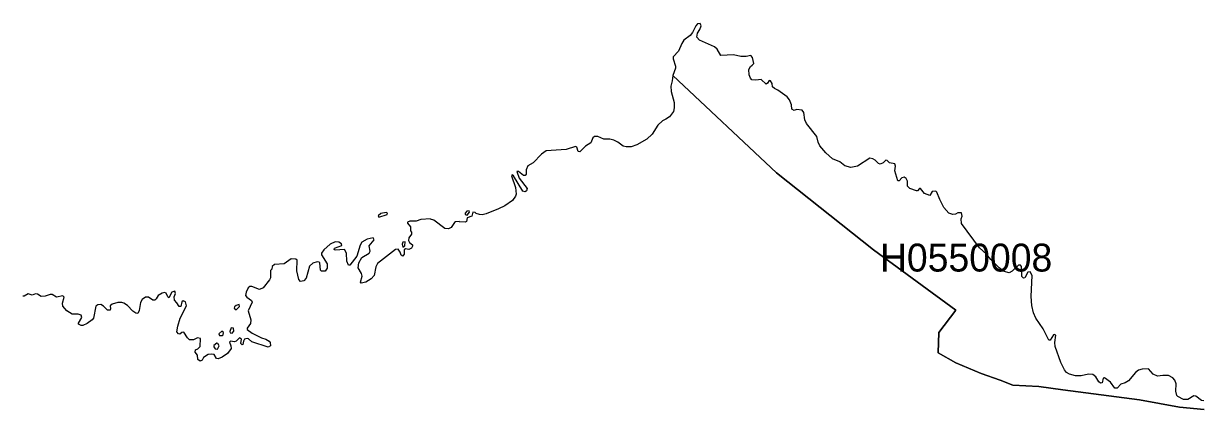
# Model space of a CAD drawing. Extents: x 369010 to 739155, y 6377141 to 6616555.
# Drawn here: x 432217 to 436436, y 6497667 to 6499050 of the extents above; entities that cross this region are included whole.
import ezdxf
from ezdxf.enums import TextEntityAlignment as Align

# ---------------------------------------------------------------- set-up
doc = ezdxf.new("R2010")
doc.units = 0
doc.header["$LTSCALE"] = 40
doc.layers.add('1', color=7, linetype='Continuous', lineweight=13)
doc.layers.add('2', color=7, linetype='Continuous')

msp = doc.modelspace()

# ---------------------------------------------------------------- linework, layer by layer
at = {"layer": '1'}
for points in [[(435305.81, 6498560.18), (435296.05, 6498551.24), (435285.12, 6498546.11), (435278.67, 6498548.27), (435267.08, 6498560.84), (435259.31, 6498565.81), (435248.05, 6498567.96), (435203.86, 6498539), (435180.03, 6498534.2), (435158.84, 6498540.65), (435140.14, 6498554.39), (435114.32, 6498565.15), (435090.16, 6498586.33), (435069.47, 6498612.15), (435063.02, 6498624.4), (435057.89, 6498645.09), (435021.14, 6498692.09), (435015.02, 6498705), (435011.21, 6498730.82), (435006.25, 6498739.42), (434985.06, 6498742.4), (434977.62, 6498739.09), (434968.51, 6498743.39), (434967.69, 6498759.12), (434960.9, 6498776.83), (434951.47, 6498786.92), (434918.37, 6498811.09), (434906.12, 6498816.88), (434900, 6498823.66), (434898.01, 6498834.92), (434892.55, 6498844.85), (434887.09, 6498846.17), (434881.62, 6498836.57), (434877.32, 6498833.26), (434858.95, 6498849.48), (434839.59, 6498847.17), (434825.52, 6498848.82), (434820.06, 6498853.95), (434815.42, 6498866.86), (434814.43, 6498885.23), (434820.22, 6498896.82), (434826.68, 6498900.62), (434832.3, 6498907.41), (434827.67, 6498928.43), (434822.21, 6498936.04), (434804.83, 6498932.23), (434785.47, 6498931.9), (434759.65, 6498938.03), (434714.63, 6498936.04), (434701.06, 6498958.72), (434691.96, 6498966.66), (434638.17, 6498990.99), (434627.91, 6499000.92), (434631.05, 6499016.31), (434639.16, 6499029.22), (434643.63, 6499042.13), (434639.82, 6499050.24), (434631.05, 6499048.92), (434624.6, 6499041.8), (434612.35, 6499018.3), (434604.57, 6499007.7), (434582.39, 6498990.33), (434574.95, 6498978.41), (434563.03, 6498950.94), (434544, 6498930.91), (434543.33, 6498923.63), (434552.44, 6498897.81), (434552.11, 6498890.69), (434542.84, 6498864.38)], [(434542.84, 6498864.38), (434542.67, 6498864.21), (434540.52, 6498844.85), (434534.73, 6498825.48), (434536.88, 6498806.29), (434547.31, 6498767.56), (434547.31, 6498748.19), (434544.66, 6498735.29), (434530.43, 6498716.09), (434517.85, 6498707.15), (434505.1, 6498701.36), (434488.72, 6498686.3), (434468.53, 6498653.69), (434448.83, 6498635.65), (434412.92, 6498615.46), (434393.39, 6498608.18), (434375.68, 6498608.18), (434364.26, 6498610.83), (434345.89, 6498624.89), (434330.66, 6498632.67), (434316.93, 6498635.32), (434295.24, 6498635.98), (434273.73, 6498644.75), (434262.31, 6498645.75), (434256.35, 6498640.29), (434248.24, 6498622.91), (434229.21, 6498610.5), (434209.35, 6498590.3), (434203.89, 6498590.97), (434198.26, 6498606.52), (434193.29, 6498609.5), (434160.69, 6498598.74), (434088.86, 6498593.78), (434071.81, 6498582.03), (434041.69, 6498550.75), (434023.49, 6498539.99), (434016.54, 6498525.26), (434016.87, 6498510.86), (434013.39, 6498504.9), (434007.1, 6498505.9), (433989.56, 6498519.63), (433983.27, 6498519.96), (433991.71, 6498495.8), (434020.84, 6498459.22), (434018.85, 6498450.12), (434013.72, 6498446.48), (434004.78, 6498448.96), (433971.68, 6498504.41), (433966.72, 6498507.55), (433964.57, 6498503.75), (433979.3, 6498462.53), (433981.61, 6498439.03), (433978.97, 6498431.09), (433967.88, 6498415.86), (433940.73, 6498396.83), (433918.23, 6498385.74), (433873.21, 6498367.7), (433859.47, 6498364.23), (433849.71, 6498365.22), (433837.63, 6498369.69), (433833.98, 6498373), (433825.54, 6498373.66), (433821.9, 6498359.59), (433806.18, 6498353.3), (433803.53, 6498340.39), (433799.39, 6498337.74), (433778.71, 6498339.07), (433777.38, 6498340.89), (433763.65, 6498339.07), (433759.84, 6498336.42), (433748.42, 6498318.71), (433739.15, 6498313.91), (433725.41, 6498316.06), (433686.36, 6498345.85), (433674.77, 6498348.5), (433673.94, 6498350.49), (433639.19, 6498347.84), (433623.63, 6498341.55), (433599.96, 6498342.21), (433592.51, 6498338.08), (433591.52, 6498334.43), (433602.94, 6498321.36), (433602.61, 6498307.62), (433606.58, 6498301.83), (433606.25, 6498295.54), (433596.49, 6498281.47), (433595.16, 6498272.37), (433599.63, 6498264.76), (433609.56, 6498256.98), (433610.22, 6498252.18), (433605.92, 6498244.57), (433596.82, 6498240.59), (433585.4, 6498242.58), (433580.43, 6498238.77), (433579.77, 6498221.73), (433577.45, 6498221.06), (433578.12, 6498218.42), (433575.8, 6498216.43), (433569.01, 6498219.74), (433565.37, 6498230.5)], [(436446.13, 6497666.79), (436357.09, 6497675.56), (436214.43, 6497701.88), (435939.2, 6497736.8), (435853.46, 6497748.55), (435760.62, 6497753.35), (435715.43, 6497772.38), (435646.42, 6497796.22), (435556.05, 6497834.28), (435492.33, 6497870.03), (435494.98, 6497942.69), (435556.05, 6498022.96), (435260.96, 6498238.44), (434914.06, 6498514.83), (434542.84, 6498864.38), (434542.84, 6498864.38)], [(434542.84, 6498864.38), (434542.84, 6498864.38), (434914.06, 6498514.83), (435260.96, 6498238.44), (435556.05, 6498022.96), (435494.98, 6497942.69), (435492.33, 6497870.03), (435556.05, 6497834.28), (435646.42, 6497796.22), (435715.43, 6497772.38), (435760.62, 6497753.35), (435853.46, 6497748.55), (435939.2, 6497736.8), (436214.43, 6497701.88), (436357.09, 6497675.56), (436446.13, 6497666.79)], [(436435.71, 6497698.57), (436416.01, 6497714.79), (436408.56, 6497715.95), (436386.88, 6497702.54), (436371.49, 6497703.04), (436351.13, 6497713.13), (436347.66, 6497717.27), (436344.35, 6497732.83), (436345.34, 6497758.48), (436340.21, 6497771.39), (436333.43, 6497780.16), (436317.37, 6497788.27), (436298.01, 6497788.6), (436278.64, 6497785.95), (436263.42, 6497793.73), (436246.04, 6497812.43), (436223.86, 6497811.77), (436210.95, 6497807.3), (436199.7, 6497799.19), (436174.21, 6497769.24), (436162.63, 6497761.79), (436146.74, 6497757.65), (436133.83, 6497742.76), (436125.55, 6497742.76), (436109.66, 6497764.27), (436088.48, 6497780.16), (436084.34, 6497779.5), (436080.04, 6497761.79), (436074.25, 6497760.8), (436068.45, 6497765.27), (436057.2, 6497784.3), (436047.27, 6497792.41), (436031.71, 6497793.4), (436005.23, 6497786.95), (435984.71, 6497787.61), (435963.36, 6497793.4), (435953.1, 6497799.53), (435945.32, 6497808.79), (435932.74, 6497834.61), (435912.38, 6497892.7), (435911.23, 6497906.77), (435914.7, 6497933.25), (435908.91, 6497935.57), (435905.43, 6497934.58), (435894.34, 6497915.21), (435889.54, 6497915.54), (435869.52, 6497955.26), (435843.2, 6497993.83), (435834.1, 6498013.19), (435828.64, 6498039.01), (435825.99, 6498071.95), (435829.96, 6498147.58), (435822.85, 6498160.16), (435814.07, 6498158.67), (435803.15, 6498138.64), (435798.02, 6498137.32), (435792.89, 6498143.44), (435790.9, 6498179.85), (435787.43, 6498183.49), (435780.64, 6498183.99), (435757.47, 6498162.48), (435747.05, 6498156.68), (435729.01, 6498161.81), (435710.97, 6498175.05), (435682, 6498204.02), (435666.11, 6498223.71), (435640.96, 6498245.89), (435576.91, 6498333.61), (435575.25, 6498350.32), (435578.73, 6498359.76), (435576.58, 6498372), (435563.67, 6498372), (435554.9, 6498366.87), (435544.96, 6498365.22), (435531.39, 6498370.02), (435513.68, 6498391.04), (435498.29, 6498419.34), (435488.2, 6498446.15), (435484.39, 6498449.29), (435471.81, 6498448.47), (435463.04, 6498434.23), (435444.01, 6498441.02), (435429.94, 6498459.39), (435425.97, 6498459.39), (435419.18, 6498450.29), (435415.38, 6498449.96), (435391.54, 6498458.73), (435383.43, 6498467.67), (435382.44, 6498485.21), (435378.3, 6498494.48), (435371.19, 6498499.94), (435362.25, 6498496.79), (435353.15, 6498486.04), (435348.68, 6498486.04), (435337.42, 6498522.61), (435340.24, 6498538.67), (435338.25, 6498546.78), (435318.06, 6498550.91), (435310.28, 6498559.02), (435305.81, 6498560.18)], [(433565.37, 6498230.5), (433558.92, 6498241.26), (433548.66, 6498239.93), (433484.77, 6498190.61), (433478.15, 6498178.2), (433472.36, 6498146.92), (433461.44, 6498135.5), (433442.57, 6498123.42), (433426.18, 6498119.44), (433424.2, 6498123.09), (433429.49, 6498144.27), (433426.84, 6498154.04), (433415.43, 6498174.06), (433417.41, 6498192.6), (433428.5, 6498211.3), (433454.32, 6498227.52), (433458.29, 6498234.47), (433454.65, 6498253.34), (433472.03, 6498275.35), (433469.38, 6498281.47), (433447.2, 6498277.34), (433428.17, 6498266.41), (433422.54, 6498255.32), (433410.13, 6498216.1), (433385.63, 6498183.83), (433380.17, 6498183.83), (433374.21, 6498197.89), (433373.22, 6498227.02), (433366.1, 6498239.93), (433332.84, 6498237.78), (433329.86, 6498239.93), (433330.52, 6498245.56), (433356.34, 6498254.99), (433355.68, 6498260.95), (433346.41, 6498266.74), (433333.17, 6498267.74), (433315.13, 6498259.63), (433292.29, 6498239.6), (433283.68, 6498226.69), (433284.01, 6498221.4), (433304.7, 6498188.79), (433304.04, 6498173.07), (433297.09, 6498161.98), (433284.01, 6498162.31), (433280.87, 6498166.45), (433278.55, 6498192.27), (433275.57, 6498194.91), (433268.13, 6498195.91), (433253.07, 6498190.94), (433240.65, 6498180.52), (433228.9, 6498137.82), (433220.13, 6498127.55), (433208.55, 6498126.07), (433202.42, 6498132.52), (433195.8, 6498163.97), (433196.46, 6498201.7), (433192.33, 6498205.34), (433175.61, 6498206.67), (433149.79, 6498188.46), (433115.86, 6498186.8), (433107.59, 6498179.85), (433105.77, 6498169.76), (433101.46, 6498164.79), (433101.79, 6498139.14), (433098.15, 6498131.2), (433074.65, 6498102.73), (433062.24, 6498097.27), (433034.43, 6498108.03), (433026.99, 6498108.03), (433021.03, 6498103.39), (433013.58, 6498086.84), (433012.26, 6498075.75), (433016.56, 6498069.13), (433033.77, 6498057.38), (433036.09, 6498051.42), (433021.03, 6498020.8), (433030.63, 6497987.7), (433029.3, 6497974.46), (433017.88, 6497958.41), (433017.88, 6497953.11), (433035.43, 6497940.37), (433069.36, 6497923.49), (433084.09, 6497919.19), (433096.17, 6497911.41), (433100.14, 6497906.44), (433101.13, 6497894.69), (433092.36, 6497890.39), (433034.77, 6497909.42), (433022.35, 6497919.85), (433017.88, 6497921.5), (433008.62, 6497918.19), (433004.81, 6497911.74), (433002.49, 6497899.82), (432999.84, 6497898.83), (432995.54, 6497903.46), (432996.87, 6497918.52), (432990.41, 6497923.82), (432978, 6497911.9), (432971.71, 6497908.76), (432957.64, 6497911.9)], [(432219, 6498072.44), (432214.36, 6498072.44)], [(432957.64, 6497911.9), (432954.17, 6497908.1), (432959.3, 6497894.69), (432960.29, 6497885.59), (432946.88, 6497867.88), (432927.68, 6497854.8), (432913.45, 6497848.51), (432907.33, 6497850), (432899.88, 6497863.58), (432889.78, 6497865.23), (432878.36, 6497863.58), (432860.66, 6497852.49), (432856.68, 6497844.05), (432849.9, 6497840.07), (432841.13, 6497845.7), (432839.47, 6497861.92), (432831.86, 6497871.85), (432832.19, 6497880.62), (432841.46, 6497884.59), (432849.57, 6497892.7), (432850.23, 6497920.84), (432839.8, 6497923.49), (432825.07, 6497915.87), (432811.34, 6497916.54), (432804.05, 6497923.49), (432790.48, 6497944.01), (432783.86, 6497942.36), (432776.75, 6497937.06), (432771.78, 6497937.72), (432765.99, 6497945), (432768.8, 6497965.2), (432778.07, 6497994.65), (432800.25, 6498038.18), (432796.61, 6498052.42), (432788.83, 6498055.73), (432783.86, 6498053.08), (432780.55, 6498035.53), (432774.1, 6498035.53), (432765.99, 6498049.27), (432757.05, 6498058.7), (432755.73, 6498070.46), (432761.02, 6498082.21), (432759.04, 6498090.32), (432747.62, 6498087.17), (432736.53, 6498067.48), (432732.89, 6498070.79), (432727.76, 6498083.53), (432721.47, 6498085.52), (432713.03, 6498083.86), (432699.29, 6498075.75), (432692.01, 6498063.34), (432686.88, 6498058.37), (432680.26, 6498058.37), (432664.37, 6498069.79), (432653.44, 6498069.46), (432642.02, 6498061.02), (432635.57, 6498050.76), (432630.94, 6498022.13), (432625.47, 6498011.37), (432618.85, 6498012.03), (432607.77, 6498018.82), (432589.56, 6498039.01), (432576.15, 6498048.28), (432568.87, 6498050.43), (432554.47, 6498050.76), (432533.62, 6498044.31), (432526.67, 6498038.35), (432528.65, 6498027.26), (432527, 6498022.79), (432517.23, 6498022.46), (432503.5, 6498036.53), (432493.73, 6498043.31), (432483.31, 6498042.32), (432475.53, 6498037.52), (432466.92, 6497994.32), (432462.78, 6497988.03), (432444.08, 6497974.63), (432428.69, 6497967.18), (432423.23, 6497967.18), (432413.96, 6497972.81), (432413.63, 6497976.28), (432425.71, 6497996.64), (432423.56, 6498005.41), (432412.8, 6498008.06), (432390.46, 6498008.06), (432371.59, 6498020.14), (432357.19, 6498036.86), (432356.2, 6498047.62), (432362.32, 6498069.46), (432357.52, 6498074.1), (432334.35, 6498069.46), (432319.62, 6498078.57), (432311.68, 6498079.23), (432294.47, 6498072.77), (432280.07, 6498071.78), (432266.33, 6498079.89), (432259.21, 6498081.54), (432247.13, 6498076.25), (432232.73, 6498080.88), (432219, 6498072.44)], [(436444.98, 6497697.58), (436435.71, 6497698.57)]]:
    msp.add_lwpolyline(points, dxfattribs=at)
for points in [[(433515.72, 6498373.33), (433496.52, 6498368.69), (433487.25, 6498361.25), (433489.24, 6498355.62), (433519.03, 6498365.22), (433520.35, 6498371.01)], [(433804.69, 6498377.3), (433798.73, 6498370.68), (433798.07, 6498365.55), (433805.85, 6498363.89), (433814.29, 6498373.99), (433812.47, 6498378.46)], [(433584.07, 6498267.74), (433575.47, 6498266.74), (433572.32, 6498259.3), (433575.3, 6498248.54), (433582.25, 6498253.34)], [(432988.92, 6498042.65), (432978.33, 6498040), (432972.37, 6498034.87), (432970.72, 6498029.58), (432974.36, 6498025.6), (432979.98, 6498025.11), (432990.41, 6498035.53)], [(432926.36, 6497947.98), (432916.27, 6497938.38), (432918.42, 6497931.6), (432928.35, 6497931.6), (432931.16, 6497934.91), (432932.82, 6497942.69)], [(432956.98, 6497941.86), (432964.26, 6497940.04), (432969.39, 6497947.65), (432968.4, 6497958.74), (432960.62, 6497959.4), (432955.65, 6497945.67)], [(432908.65, 6497904.12), (432898.56, 6497896.01), (432898.56, 6497891.05), (432903.52, 6497884.59), (432911.3, 6497882.94), (432916.93, 6497894.69), (432912.62, 6497903.13)]]:
    msp.add_lwpolyline(points, close=True, dxfattribs=at)

# ---------------------------------------------------------------- texts
at = {"layer": '2'}
msp.add_text('H0550008', height=100, dxfattribs=at).set_placement((435592.95, 6498161.2), align=Align.CENTER)

doc.saveas('drawing.dxf')
